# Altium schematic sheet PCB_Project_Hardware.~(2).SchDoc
size 431 x 279 mm; Date: Not shown in title block; ApprovedBy: Not shown in title block; CheckedBy: Not shown in title block; Author: Not shown in title block; CompanyName: Not shown in title block; Engineer: Not shown in title block; Organization: Not shown in title block; Address1: Not shown in title block; Address2: Not shown in title block; Address3: Not shown in title block; Address4: Not shown in title block; DocumentNumber: 3; Revision: Use project parameter SCH_Rev; SheetNumber: 3; SheetTotal: 4; PageSetup: Record=PageOptions¦CenterHorizontal=True¦CenterVertical=True¦PrintScale=1.00¦XCorrection=1.00¦YCorrection=1.00¦PrintKind=0¦BorderSize=5000000¦LeftOffset=0¦BottomOffset=0¦Orientation=2¦PaperLength=1000¦PaperWidth=1000¦Scale=100¦PaperSource=15¦PrintQuality=600¦MediaType=1¦DitherType=10¦PaperKind=Letter¦PrintScaleMode=1
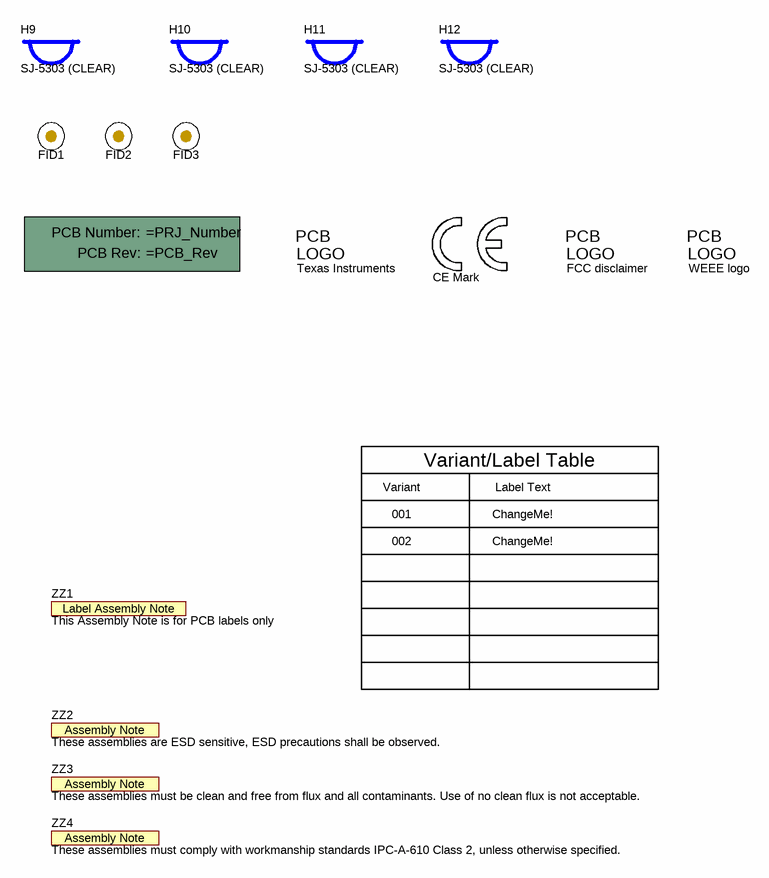
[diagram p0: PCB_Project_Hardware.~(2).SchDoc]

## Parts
!PCB  Printed Circuit Board  (value not drawn)  (mechanical)
FID1  Fiducial  [Fiducial10-20]  (value not drawn)
FID2  Fiducial  [Fiducial10-20]  (value not drawn)
FID3  Fiducial  [Fiducial10-20]  (value not drawn)
H9  SJ-5303 (CLEAR)  [Bumpon_SJ5003Transparent]
H10  SJ-5303 (CLEAR)  [Bumpon_SJ5003Transparent]
H11  SJ-5303 (CLEAR)  [Bumpon_SJ5003Transparent]
H12  SJ-5303 (CLEAR)  [Bumpon_SJ5003Transparent]
Logo1  Texas Instruments  [TI_Stacked_Overlay_Small]  (no BOM)
Logo2  CE Mark  [CE_Mark_5mm]  (no BOM)
Logo3  FCC disclaimer  [FCC_disclaimer]  (no BOM)
Logo4  WEEE logo  [WEEE_Minimum]  (no BOM)
ZZ1  This Assembly Note is for PCB labels only  [AssemblyNoteLabel]  (no BOM)
ZZ2  These assemblies are ESD sensitive, ESD precautions shall be observed.  [AssemblyNote]  (no BOM)
ZZ3  These assemblies must be clean and free from flux and all contaminants. Use of no clean flux is not acceptable.  [AssemblyNote]  (no BOM)
ZZ4  These assemblies must comply with workmanship standards IPC-A-610 Class 2, unless otherwise specified.  [AssemblyNote]  (no BOM)

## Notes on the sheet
- Variant
- Variant/Label Table
- Label Text
- 001
- 002
- ChangeMe!

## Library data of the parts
!PCB = CMP-0003618-2: Manufacturer: Any
FID1-FID3 = CMP-0077181-1: Fiducial mark.  There is nothing to buy or mount.
H9-H12 = CMP-0003620-1: Bumpon, Hemisphere, 0.44 X 0.20, Clear; Manufacturer: 3M
Logo1 = CMP-0074838-1: Texas Instrument Corporate Signature; SymbolCreator: a0412235; Lib Reference: TI_Logo; Library Reference: Logo
Logo2 = CMP-0074844-1: SymbolCreator: a0412235
Logo3 = CMP-0074847-1: FCC_disclaimer; Library Reference: Logo
Logo4 = CMP-0074769-1
ZZ1 = CMP-0003616-3
ZZ2 = CMP-0077236-1
ZZ3 = CMP-0077237-1
ZZ4 = CMP-0077238-1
